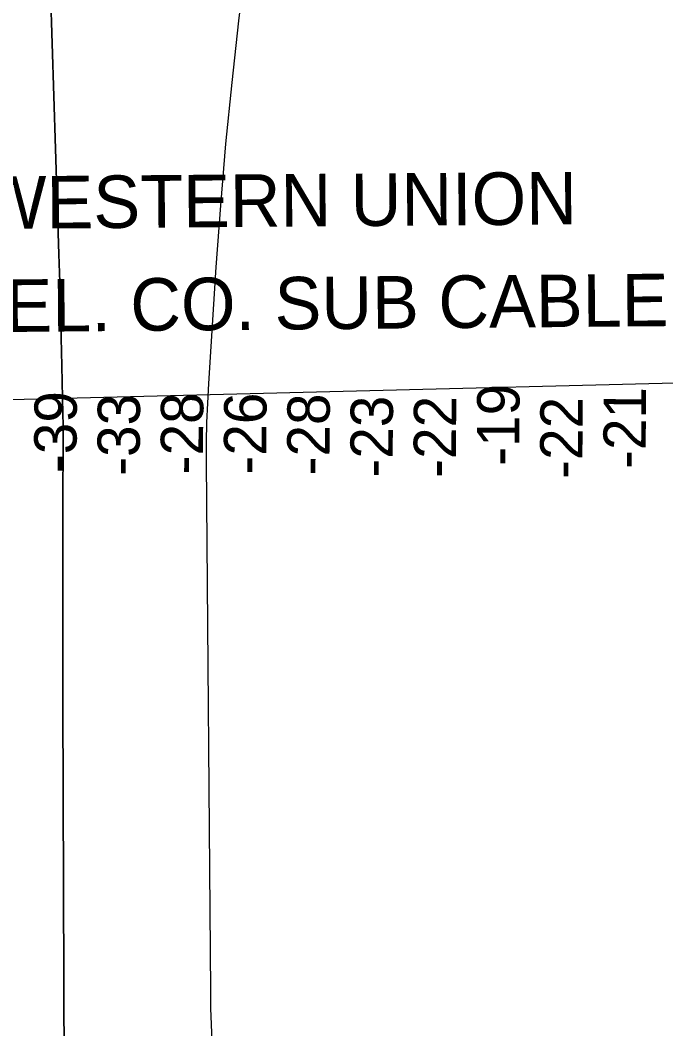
# Model space of a CAD drawing. Extents: x 3313447 to 3351316, y 703786 to 729172.
# Drawn here: x 3323342 to 3324363, y 710857 to 712451 of the extents above; entities that cross this region are included whole.
import ezdxf

# ---------------------------------------------------------------- set-up
doc = ezdxf.new("R2010")
doc.units = 0
for name, color, linetype in [('V-RIVR-RANG', 7, 'Continuous'), ('V-TOPO-DPTH', 7, 'Continuous'), ('V-TOPO-MINR', 7, 'Continuous'), ('V-UTIL-IDEN', 7, 'Continuous'), ('V-UTIL-LINE', 7, 'Continuous')]:
    doc.layers.add(name, color=color, linetype=linetype)

msp = doc.modelspace()

# ---------------------------------------------------------------- linework, layer by layer
at = {"layer": 'V-TOPO-DPTH'}
for points in [[(3323387.7, 712581.4), (3323403.5, 712081.5), (3323404.9, 712037.4), (3323406.1, 711993.4), (3323407.2, 711949.4), (3323408.1, 711905.3), (3323409.7, 711829.1), (3323409.8, 711823.2), (3323409.9, 711817.2), (3323409.9, 711811.3), (3323410, 711805.4), (3323409.6, 711669.4), (3323409.5, 711595.5), (3323409.5, 711521.6), (3323409.6, 711447.7), (3323409.8, 711373.8), (3323411.8, 710788.7)], [(3323411.8, 710788.7), (3323409.8, 711373.8), (3323409.6, 711447.7), (3323409.5, 711521.6), (3323409.5, 711595.5), (3323409.6, 711669.4), (3323410, 711805.4), (3323409.9, 711811.3), (3323409.9, 711817.2), (3323409.8, 711823.2), (3323409.7, 711829.1), (3323408.1, 711905.3), (3323407.2, 711949.4), (3323406.1, 711993.4), (3323404.9, 712037.4), (3323403.5, 712081.5), (3323387.7, 712581.4)], [(3323645.6, 710838.5), (3323644.6, 710864.4), (3323643.9, 710890.3), (3323643.5, 710916.3), (3323636.9, 711753.7), (3323637, 711784.5), (3323637.5, 711815.3), (3323638.7, 711846.1), (3323640.4, 711876.9), (3323652.3, 712060.9), (3323659.4, 712158.3), (3323667.5, 712255.7), (3323677.2, 712352.9), (3323687.9, 712450), (3323704.6, 712591.2)], [(3323645.6, 710838.5), (3323644.6, 710864.4), (3323643.9, 710890.3), (3323643.5, 710916.3), (3323636.9, 711753.7), (3323637, 711784.5), (3323637.5, 711815.3), (3323638.7, 711846.1), (3323640.4, 711876.9), (3323652.3, 712060.9), (3323659.4, 712158.3), (3323667.5, 712255.7), (3323677.2, 712352.9), (3323687.9, 712450), (3323704.6, 712591.2)]]:
    msp.add_lwpolyline(points, dxfattribs=at)
at = {"layer": 'V-TOPO-MINR'}
for points in [[(3323387.7, 712581.4), (3323403.5, 712081.5), (3323404.9, 712037.4), (3323406.1, 711993.4), (3323407.2, 711949.4), (3323408.1, 711905.3), (3323409.7, 711829.1), (3323409.8, 711823.2), (3323409.9, 711817.2), (3323409.9, 711811.3), (3323410, 711805.4), (3323409.6, 711669.4), (3323409.5, 711595.5), (3323409.5, 711521.6), (3323409.6, 711447.7), (3323409.8, 711373.8), (3323411.8, 710788.7)], [(3323645.6, 710838.5), (3323644.6, 710864.4), (3323643.9, 710890.3), (3323643.5, 710916.3), (3323636.9, 711753.7), (3323637, 711784.5), (3323637.5, 711815.3), (3323638.7, 711846.1), (3323640.4, 711876.9), (3323652.3, 712060.9), (3323659.4, 712158.3), (3323667.5, 712255.7), (3323677.2, 712352.9), (3323687.9, 712450), (3323704.6, 712591.2)]]:
    msp.add_lwpolyline(points, dxfattribs=at)
at = {"layer": 'V-UTIL-LINE'}
msp.add_line((3322220, 711823.9), (3325517.1, 711906.7), dxfattribs=at)

# ---------------------------------------------------------------- texts
at = {"layer": 'V-RIVR-RANG'}
for s, p in [('-19', (3324131.2, 711746.9)), ('-21', (3324331.2, 711742)), ('-39', (3323431.1, 711735.4)), ('-33', (3323531.1, 711731.1)), ('-28', (3323631.1, 711733.4)), ('-26', (3323731.1, 711733.1)), ('-28', (3323831.1, 711731.7)), ('-23', (3323931.1, 711728.3)), ('-22', (3324031.1, 711727.9)), ('-22', (3324231.1, 711726.3))]:
    msp.add_text(s, height=67, rotation=89.6585, dxfattribs=at).set_placement(p)
at = {"layer": 'V-UTIL-IDEN'}
for s, rotation, p in [('WESTERN UNION', 0.4525, (3323279.4, 712121.2)), ('TEL. & TEL. CO. SUB CABLE', 0.5089, (3322881.3, 711954.6))]:
    msp.add_text(s, height=83, rotation=rotation, dxfattribs=at).set_placement(p)

doc.saveas('drawing.dxf')
